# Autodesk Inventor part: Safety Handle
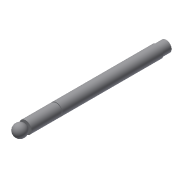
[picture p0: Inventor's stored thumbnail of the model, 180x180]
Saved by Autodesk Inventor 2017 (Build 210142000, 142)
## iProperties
Shininess: 77.0
Length Units: 11269
Angle Units: 11279
Time Units: 11290
Mass Units: 11283
Length Display Precision: 3
Angle Display Precision: 2
Created: 2002-02
Part Number: Safety Handle
Document SubType Name: Modeling
Designer: ***
Density: 1 g/cm^3
Material: Generic
Mass: 54.3914 g
Surface Area: 130.219 cm^2
Volume: 54.3914 cm^3
Appearance: Default
Density: 0.0
Volumn: 0.0
Area: 0.0
PropertySet Name: Model Information
Control State: 0
Master: False
Checked Out: False
Author: ***
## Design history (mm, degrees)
sketch "Sketch1"
  geometry: L1 (0, 205)-(8, 205); L2 (8, 205)-(8, 192); L3 (8, 192)-(9, 192); L4 (9, 192)-(9, 45); L5 (9, 45)-(8, 45); L6 (8, 45)-(8, 43); L7 (8, 43)-(9, 43); L8 (9, 43)-(9, 0); L9 (9, 0)-(0, 0); L10 (0, 0)-(0, 205)
  constraints: 20 end point, 7 parallel, 1 collinear, 1 horizontal, 1 perpendicular
  dimensions: "d0" = 13 distance of L1.end L2.end; "d1" = 2 distance of L4.end L7.end; "d2" = 43 distance of L7.end L8.end; "d3" = 205 distance of L9.end L1.start; "d4" = 16 diameter of L2 L10; "d5" = 18 diameter of L4 L10; "d6" = 16 diameter of L6.end L10
revolve "Revolution1" sketch "Sketch1" stored, may be unused: angle "d7" = 90 deg
sketch "Sketch2"
  geometry: L1 (0, 1)-(0, -17); L2 (-9, 0)-(9, 0) reference; A1 r 9 centre (0, -8) between (0, -17) and (0, 1)
  constraints: 2 end point, 2 point on circle, 1 centre point, 1 midpoint, 1 vertical
  dimensions: "d8" = 9 radius of A1; "d9" = 1 distance from line of L2 L1.start
revolve "Revolution2" sketch "Sketch2" stored, may be unused: angle "d10" = 90 deg
body "Solid1"
